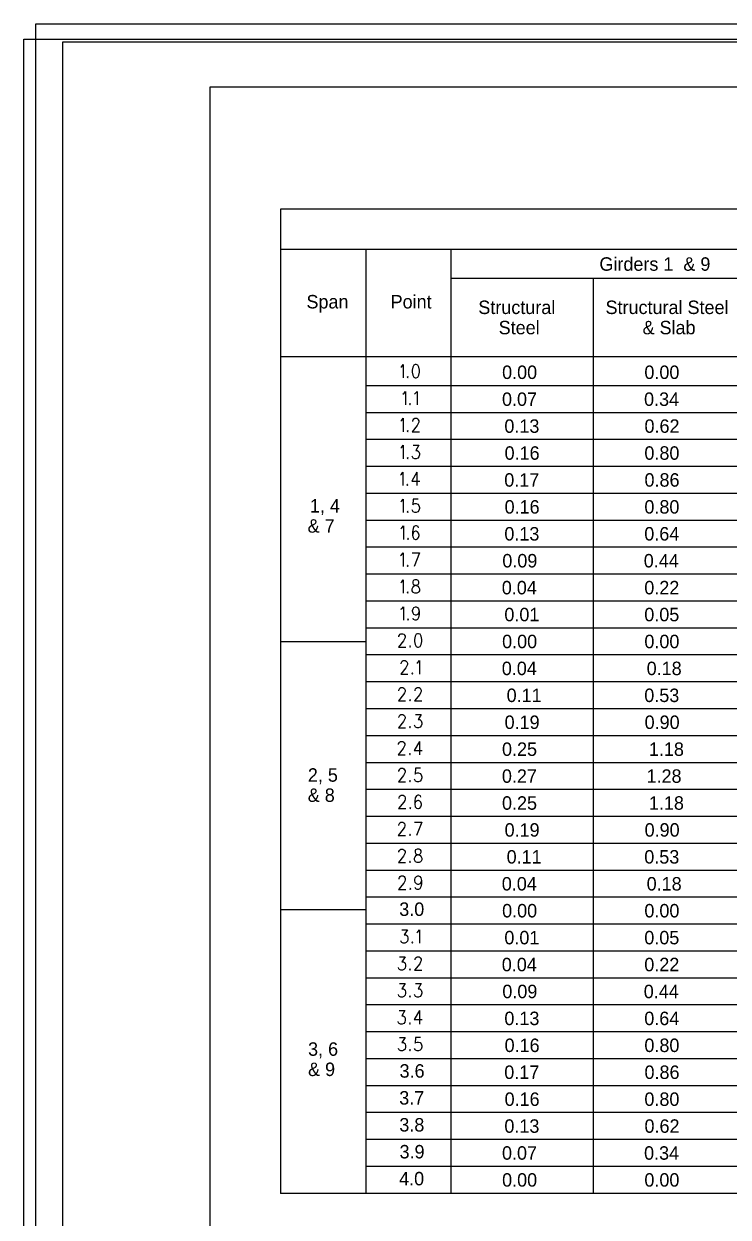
# Model space of a CAD drawing. Extents: x -725.7 to -683.7, y 85.6 to 107.6.
# Drawn here: x -725.67 to -719.13, y 96.51 to 107.6 of the extents above; entities that cross this region are included whole.
import ezdxf

# ---------------------------------------------------------------- set-up
doc = ezdxf.new("R2010")
doc.units = 0
for name, color, linetype in [('border', 7, 'Continuous'), ('Border 2660-Hwy18 - Level 62', 7, 'Continuous'), ('Border 2660-Hwy18 - Level 63', 7, 'Continuous'), ('Level 62 PDF', 7, 'Continuous'), ('Steel', 7, 'Continuous'), ('Text', 7, 'Continuous')]:
    doc.layers.add(name, color=color, linetype=linetype)

msp = doc.modelspace()

# ---------------------------------------------------------------- linework, layer by layer
at = {"layer": 'border'}
for p, q in [((-723.942, 107.01), (-691.93, 107.01)), ((-723.942, 86.465), (-723.942, 107.01))]:
    msp.add_line(p, q, dxfattribs=at)
at = {"layer": 'Border 2660-Hwy18 - Level 62'}
msp.add_lwpolyline([(-725.562, 107.596), (-691.443, 107.596), (-691.443, 85.786), (-725.562, 85.786)], close=True, dxfattribs=at)
at = {"layer": 'Border 2660-Hwy18 - Level 63'}
msp.add_lwpolyline([(-725.673, 107.453), (-691.673, 107.453), (-691.673, 86.083), (-725.673, 86.083)], close=True, dxfattribs=at)
at = {"layer": 'Level 62 PDF'}
msp.add_lwpolyline([(-725.312, 107.429), (-691.193, 107.429), (-691.193, 85.62), (-725.312, 85.62)], close=True, dxfattribs=at)
at = {"layer": 'Steel'}
for p, q in [((-723.289, 105.876), (-723.289, 96.735)), ((-709.806, 105.876), (-723.289, 105.876)), ((-709.806, 105.499), (-723.289, 105.499)), ((-722.496, 105.499), (-722.496, 96.735)), ((-721.704, 105.499), (-721.704, 96.735)), ((-709.806, 105.23), (-721.704, 105.23)), ((-720.382, 105.23), (-720.382, 96.735)), ((-709.806, 104.503), (-723.289, 104.503)), ((-709.806, 104.235), (-722.496, 104.235)), ((-709.806, 103.985), (-722.496, 103.985)), ((-709.806, 103.735), (-722.496, 103.735)), ((-709.806, 103.485), (-722.496, 103.485)), ((-709.806, 103.235), (-722.496, 103.235)), ((-709.806, 102.985), (-722.496, 102.985)), ((-709.806, 102.735), (-722.496, 102.735)), ((-709.806, 102.485), (-722.496, 102.485)), ((-709.806, 102.235), (-722.496, 102.235)), ((-709.806, 101.985), (-722.496, 101.985)), ((-722.496, 101.857), (-723.289, 101.857)), ((-709.806, 101.735), (-722.496, 101.735)), ((-709.806, 101.485), (-722.496, 101.485)), ((-709.806, 101.235), (-722.496, 101.235)), ((-709.806, 100.985), (-722.496, 100.985)), ((-709.806, 100.735), (-722.496, 100.735)), ((-709.806, 100.485), (-722.496, 100.485)), ((-709.806, 100.235), (-722.496, 100.235)), ((-709.806, 99.985), (-722.496, 99.985)), ((-709.806, 99.735), (-722.496, 99.735)), ((-709.806, 99.485), (-722.496, 99.485)), ((-722.496, 99.367), (-723.289, 99.367)), ((-709.806, 99.235), (-722.496, 99.235)), ((-709.806, 98.985), (-722.496, 98.985)), ((-709.806, 98.735), (-722.496, 98.735)), ((-709.806, 98.485), (-722.496, 98.485)), ((-709.806, 98.235), (-722.496, 98.235)), ((-709.806, 97.985), (-722.496, 97.985)), ((-709.806, 97.735), (-722.496, 97.735)), ((-709.806, 97.485), (-722.496, 97.485)), ((-709.806, 97.235), (-722.496, 97.235)), ((-709.806, 96.985), (-722.496, 96.985)), ((-709.806, 96.735), (-723.289, 96.735))]:
    msp.add_line(p, q, dxfattribs=at)
at = {"layer": 'Text'}
for p, q in [((-722.02, 103.433), (-722.02, 103.308)), ((-722.064, 102.683), (-721.997, 102.683)), ((-721.997, 102.683), (-722.045, 102.558)), ((-721.998, 100.933), (-721.998, 100.808)), ((-722.043, 100.183), (-721.976, 100.183)), ((-721.976, 100.183), (-722.024, 100.058)), ((-721.998, 98.433), (-721.998, 98.308))]:
    msp.add_line(p, q, dxfattribs=at)
for points in [[(-722.171, 104.408), (-722.161, 104.415), (-722.147, 104.433), (-722.147, 104.308)], [(-722.036, 104.433), (-722.05, 104.427), (-722.06, 104.408), (-722.064, 104.379), (-722.064, 104.361), (-722.06, 104.332), (-722.05, 104.314), (-722.036, 104.308), (-722.027, 104.308), (-722.012, 104.314), (-722.002, 104.332), (-721.997, 104.361), (-721.997, 104.379), (-722.002, 104.408), (-722.012, 104.427), (-722.027, 104.433), (-722.036, 104.433)], [(-722.105, 104.32), (-722.11, 104.314), (-722.105, 104.308), (-722.101, 104.314), (-722.105, 104.32)], [(-722.15, 104.158), (-722.14, 104.165), (-722.126, 104.183), (-722.126, 104.058)], [(-722.043, 104.158), (-722.033, 104.165), (-722.019, 104.183), (-722.019, 104.058)], [(-722.084, 104.07), (-722.089, 104.064), (-722.084, 104.058), (-722.08, 104.064), (-722.084, 104.07)], [(-722.171, 103.908), (-722.162, 103.915), (-722.148, 103.933), (-722.148, 103.808)], [(-722.06, 103.903), (-722.06, 103.908), (-722.055, 103.92), (-722.05, 103.927), (-722.041, 103.933), (-722.022, 103.933), (-722.012, 103.927), (-722.008, 103.92), (-722.002, 103.908), (-722.002, 103.897), (-722.008, 103.885), (-722.017, 103.867), (-722.064, 103.808), (-721.997, 103.808)], [(-722.106, 103.82), (-722.111, 103.814), (-722.106, 103.808), (-722.101, 103.814), (-722.106, 103.82)], [(-722.171, 103.659), (-722.162, 103.665), (-722.148, 103.683), (-722.148, 103.558)], [(-722.055, 103.683), (-722.002, 103.683), (-722.031, 103.635), (-722.017, 103.635), (-722.008, 103.629), (-722.002, 103.623), (-721.997, 103.605), (-721.997, 103.594), (-722.002, 103.576), (-722.012, 103.564), (-722.027, 103.558), (-722.041, 103.558), (-722.055, 103.564), (-722.06, 103.57), (-722.064, 103.582)], [(-722.106, 103.57), (-722.111, 103.564), (-722.106, 103.558), (-722.101, 103.564), (-722.106, 103.57)], [(-722.174, 103.409), (-722.164, 103.415), (-722.15, 103.433), (-722.15, 103.308)], [(-722.02, 103.433), (-722.067, 103.349), (-721.995, 103.349)], [(-722.108, 103.32), (-722.113, 103.314), (-722.108, 103.308), (-722.104, 103.314), (-722.108, 103.32)], [(-722.171, 103.159), (-722.162, 103.165), (-722.148, 103.183), (-722.148, 103.058)], [(-722.008, 103.183), (-722.055, 103.183), (-722.06, 103.129), (-722.055, 103.135), (-722.041, 103.141), (-722.027, 103.141), (-722.012, 103.135), (-722.002, 103.123), (-721.997, 103.105), (-721.997, 103.094), (-722.002, 103.076), (-722.012, 103.064), (-722.027, 103.058), (-722.041, 103.058), (-722.055, 103.064), (-722.06, 103.07), (-722.064, 103.082)], [(-722.106, 103.07), (-722.111, 103.064), (-722.106, 103.058), (-722.101, 103.064), (-722.106, 103.07)], [(-722.169, 102.909), (-722.16, 102.915), (-722.145, 102.933), (-722.145, 102.808)], [(-722.005, 102.915), (-722.01, 102.927), (-722.024, 102.933), (-722.034, 102.933), (-722.048, 102.927), (-722.057, 102.909), (-722.062, 102.879), (-722.062, 102.849), (-722.057, 102.826), (-722.048, 102.814), (-722.034, 102.808), (-722.029, 102.808), (-722.015, 102.814), (-722.005, 102.826), (-722, 102.844), (-722, 102.849), (-722.005, 102.867), (-722.015, 102.879), (-722.029, 102.885), (-722.034, 102.885), (-722.048, 102.879), (-722.057, 102.867), (-722.062, 102.849)], [(-722.104, 102.82), (-722.108, 102.814), (-722.104, 102.808), (-722.099, 102.814), (-722.104, 102.82)], [(-722.172, 102.659), (-722.163, 102.665), (-722.149, 102.683), (-722.149, 102.558)], [(-722.107, 102.57), (-722.112, 102.564), (-722.107, 102.558), (-722.102, 102.564), (-722.107, 102.57)], [(-722.171, 102.409), (-722.162, 102.415), (-722.148, 102.433), (-722.148, 102.308)], [(-722.041, 102.433), (-722.055, 102.427), (-722.06, 102.415), (-722.06, 102.403), (-722.055, 102.391), (-722.045, 102.385), (-722.027, 102.379), (-722.012, 102.373), (-722.002, 102.361), (-721.997, 102.349), (-721.997, 102.332), (-722.002, 102.32), (-722.008, 102.314), (-722.022, 102.308), (-722.041, 102.308), (-722.055, 102.314), (-722.06, 102.32), (-722.064, 102.332), (-722.064, 102.349), (-722.06, 102.361), (-722.05, 102.373), (-722.036, 102.379), (-722.017, 102.385), (-722.008, 102.391), (-722.002, 102.403), (-722.002, 102.415), (-722.008, 102.427), (-722.022, 102.433), (-722.041, 102.433)], [(-722.106, 102.32), (-722.111, 102.314), (-722.106, 102.308), (-722.101, 102.314), (-722.106, 102.32)], [(-722.169, 102.159), (-722.16, 102.165), (-722.145, 102.183), (-722.145, 102.058)], [(-722, 102.141), (-722.005, 102.123), (-722.015, 102.111), (-722.029, 102.105), (-722.034, 102.105), (-722.048, 102.111), (-722.057, 102.123), (-722.062, 102.141), (-722.062, 102.147), (-722.057, 102.165), (-722.048, 102.177), (-722.034, 102.183), (-722.029, 102.183), (-722.015, 102.177), (-722.005, 102.165), (-722, 102.141), (-722, 102.111), (-722.005, 102.082), (-722.015, 102.064), (-722.029, 102.058), (-722.038, 102.058), (-722.053, 102.064), (-722.057, 102.076)], [(-722.104, 102.07), (-722.108, 102.064), (-722.104, 102.058), (-722.099, 102.064), (-722.104, 102.07)], [(-722.188, 101.903), (-722.188, 101.909), (-722.183, 101.92), (-722.178, 101.927), (-722.169, 101.933), (-722.15, 101.933), (-722.14, 101.927), (-722.136, 101.92), (-722.13, 101.909), (-722.13, 101.897), (-722.136, 101.885), (-722.145, 101.867), (-722.192, 101.808), (-722.125, 101.808)], [(-722.014, 101.933), (-722.029, 101.927), (-722.038, 101.909), (-722.043, 101.879), (-722.043, 101.861), (-722.038, 101.832), (-722.029, 101.814), (-722.014, 101.808), (-722.005, 101.808), (-721.991, 101.814), (-721.981, 101.832), (-721.976, 101.861), (-721.976, 101.879), (-721.981, 101.909), (-721.991, 101.927), (-722.005, 101.933), (-722.014, 101.933)], [(-722.084, 101.82), (-722.088, 101.814), (-722.084, 101.808), (-722.079, 101.814), (-722.084, 101.82)], [(-722.167, 101.653), (-722.167, 101.659), (-722.162, 101.67), (-722.157, 101.677), (-722.148, 101.683), (-722.129, 101.683), (-722.119, 101.677), (-722.115, 101.67), (-722.109, 101.659), (-722.109, 101.647), (-722.115, 101.635), (-722.124, 101.617), (-722.171, 101.558), (-722.104, 101.558)], [(-722.021, 101.659), (-722.012, 101.665), (-721.997, 101.683), (-721.997, 101.558)], [(-722.063, 101.57), (-722.067, 101.564), (-722.063, 101.558), (-722.058, 101.564), (-722.063, 101.57)], [(-722.188, 101.403), (-722.188, 101.409), (-722.184, 101.42), (-722.179, 101.427), (-722.169, 101.433), (-722.151, 101.433), (-722.141, 101.427), (-722.136, 101.42), (-722.131, 101.409), (-722.131, 101.397), (-722.136, 101.385), (-722.146, 101.367), (-722.193, 101.308), (-722.126, 101.308)], [(-722.038, 101.403), (-722.038, 101.409), (-722.033, 101.42), (-722.029, 101.427), (-722.019, 101.433), (-722, 101.433), (-721.991, 101.427), (-721.986, 101.42), (-721.981, 101.409), (-721.981, 101.397), (-721.986, 101.385), (-721.995, 101.367), (-722.043, 101.308), (-721.976, 101.308)], [(-722.084, 101.32), (-722.089, 101.314), (-722.084, 101.308), (-722.08, 101.314), (-722.084, 101.32)], [(-722.188, 101.153), (-722.188, 101.159), (-722.184, 101.17), (-722.179, 101.177), (-722.169, 101.183), (-722.151, 101.183), (-722.141, 101.177), (-722.136, 101.17), (-722.131, 101.159), (-722.131, 101.147), (-722.136, 101.135), (-722.146, 101.117), (-722.193, 101.058), (-722.126, 101.058)], [(-722.033, 101.183), (-721.981, 101.183), (-722.01, 101.135), (-721.995, 101.135), (-721.986, 101.129), (-721.981, 101.123), (-721.976, 101.105), (-721.976, 101.094), (-721.981, 101.076), (-721.991, 101.064), (-722.005, 101.058), (-722.019, 101.058), (-722.033, 101.064), (-722.038, 101.07), (-722.043, 101.082)], [(-722.084, 101.07), (-722.089, 101.064), (-722.084, 101.058), (-722.08, 101.064), (-722.084, 101.07)], [(-722.191, 100.903), (-722.191, 100.909), (-722.186, 100.92), (-722.181, 100.927), (-722.172, 100.933), (-722.153, 100.933), (-722.143, 100.927), (-722.139, 100.92), (-722.133, 100.909), (-722.133, 100.897), (-722.139, 100.885), (-722.148, 100.867), (-722.195, 100.808), (-722.129, 100.808)], [(-721.998, 100.933), (-722.045, 100.849), (-721.973, 100.849)], [(-722.087, 100.82), (-722.091, 100.814), (-722.087, 100.808), (-722.082, 100.814), (-722.087, 100.82)], [(-722.188, 100.653), (-722.188, 100.659), (-722.184, 100.67), (-722.179, 100.677), (-722.169, 100.683), (-722.151, 100.683), (-722.141, 100.677), (-722.136, 100.67), (-722.131, 100.659), (-722.131, 100.647), (-722.136, 100.635), (-722.146, 100.617), (-722.193, 100.558), (-722.126, 100.558)], [(-721.986, 100.683), (-722.033, 100.683), (-722.038, 100.629), (-722.033, 100.635), (-722.019, 100.641), (-722.005, 100.641), (-721.991, 100.635), (-721.981, 100.623), (-721.976, 100.605), (-721.976, 100.594), (-721.981, 100.576), (-721.991, 100.564), (-722.005, 100.558), (-722.019, 100.558), (-722.033, 100.564), (-722.038, 100.57), (-722.043, 100.582)], [(-722.084, 100.57), (-722.089, 100.564), (-722.084, 100.558), (-722.08, 100.564), (-722.084, 100.57)], [(-722.186, 100.403), (-722.186, 100.409), (-722.181, 100.42), (-722.177, 100.427), (-722.167, 100.433), (-722.148, 100.433), (-722.139, 100.427), (-722.134, 100.42), (-722.129, 100.409), (-722.129, 100.397), (-722.134, 100.385), (-722.143, 100.367), (-722.191, 100.308), (-722.124, 100.308)], [(-721.983, 100.415), (-721.988, 100.427), (-722.003, 100.433), (-722.012, 100.433), (-722.026, 100.427), (-722.036, 100.409), (-722.04, 100.379), (-722.04, 100.349), (-722.036, 100.326), (-722.026, 100.314), (-722.012, 100.308), (-722.007, 100.308), (-721.993, 100.314), (-721.983, 100.326), (-721.978, 100.344), (-721.978, 100.349), (-721.983, 100.367), (-721.993, 100.379), (-722.007, 100.385), (-722.012, 100.385), (-722.026, 100.379), (-722.036, 100.367), (-722.04, 100.349)], [(-722.082, 100.32), (-722.087, 100.314), (-722.082, 100.308), (-722.077, 100.314), (-722.082, 100.32)], [(-722.189, 100.153), (-722.189, 100.159), (-722.184, 100.17), (-722.18, 100.177), (-722.17, 100.183), (-722.151, 100.183), (-722.142, 100.177), (-722.137, 100.17), (-722.132, 100.159), (-722.132, 100.147), (-722.137, 100.135), (-722.147, 100.117), (-722.194, 100.058), (-722.127, 100.058)], [(-722.085, 100.07), (-722.09, 100.064), (-722.085, 100.058), (-722.08, 100.064), (-722.085, 100.07)], [(-722.188, 99.903), (-722.188, 99.909), (-722.184, 99.92), (-722.179, 99.927), (-722.169, 99.933), (-722.151, 99.933), (-722.141, 99.927), (-722.136, 99.92), (-722.131, 99.909), (-722.131, 99.897), (-722.136, 99.885), (-722.146, 99.867), (-722.193, 99.808), (-722.126, 99.808)], [(-722.019, 99.933), (-722.033, 99.927), (-722.038, 99.915), (-722.038, 99.903), (-722.033, 99.891), (-722.024, 99.885), (-722.005, 99.879), (-721.991, 99.873), (-721.981, 99.861), (-721.976, 99.849), (-721.976, 99.832), (-721.981, 99.82), (-721.986, 99.814), (-722, 99.808), (-722.019, 99.808), (-722.033, 99.814), (-722.038, 99.82), (-722.043, 99.832), (-722.043, 99.849), (-722.038, 99.861), (-722.029, 99.873), (-722.014, 99.879), (-721.995, 99.885), (-721.986, 99.891), (-721.981, 99.903), (-721.981, 99.915), (-721.986, 99.927), (-722, 99.933), (-722.019, 99.933)], [(-722.084, 99.82), (-722.089, 99.814), (-722.084, 99.808), (-722.08, 99.814), (-722.084, 99.82)], [(-722.186, 99.653), (-722.186, 99.659), (-722.181, 99.67), (-722.177, 99.677), (-722.167, 99.683), (-722.148, 99.683), (-722.139, 99.677), (-722.134, 99.67), (-722.129, 99.659), (-722.129, 99.647), (-722.134, 99.635), (-722.143, 99.617), (-722.191, 99.558), (-722.124, 99.558)], [(-721.978, 99.641), (-721.984, 99.623), (-721.993, 99.611), (-722.007, 99.605), (-722.012, 99.605), (-722.026, 99.611), (-722.036, 99.623), (-722.04, 99.641), (-722.04, 99.647), (-722.036, 99.665), (-722.026, 99.677), (-722.012, 99.683), (-722.007, 99.683), (-721.993, 99.677), (-721.984, 99.665), (-721.978, 99.641), (-721.978, 99.611), (-721.984, 99.582), (-721.993, 99.564), (-722.007, 99.558), (-722.017, 99.558), (-722.031, 99.564), (-722.036, 99.576)], [(-722.082, 99.57), (-722.087, 99.564), (-722.082, 99.558), (-722.077, 99.564), (-722.082, 99.57)], [(-722.162, 99.183), (-722.109, 99.183), (-722.138, 99.135), (-722.124, 99.135), (-722.115, 99.129), (-722.109, 99.123), (-722.104, 99.105), (-722.104, 99.094), (-722.109, 99.076), (-722.119, 99.064), (-722.134, 99.058), (-722.148, 99.058), (-722.162, 99.064), (-722.167, 99.07), (-722.171, 99.082)], [(-722.021, 99.159), (-722.012, 99.165), (-721.997, 99.183), (-721.997, 99.058)], [(-722.063, 99.07), (-722.067, 99.064), (-722.063, 99.058), (-722.058, 99.064), (-722.063, 99.07)], [(-722.184, 98.933), (-722.131, 98.933), (-722.16, 98.885), (-722.146, 98.885), (-722.136, 98.879), (-722.131, 98.873), (-722.126, 98.855), (-722.126, 98.844), (-722.131, 98.826), (-722.141, 98.814), (-722.155, 98.808), (-722.169, 98.808), (-722.184, 98.814), (-722.188, 98.82), (-722.193, 98.832)], [(-722.038, 98.903), (-722.038, 98.909), (-722.033, 98.92), (-722.029, 98.927), (-722.019, 98.933), (-722, 98.933), (-721.991, 98.927), (-721.986, 98.92), (-721.981, 98.909), (-721.981, 98.897), (-721.986, 98.885), (-721.995, 98.867), (-722.043, 98.808), (-721.976, 98.808)], [(-722.084, 98.82), (-722.089, 98.814), (-722.084, 98.808), (-722.08, 98.814), (-722.084, 98.82)], [(-722.184, 98.683), (-722.131, 98.683), (-722.16, 98.635), (-722.146, 98.635), (-722.136, 98.629), (-722.131, 98.623), (-722.126, 98.605), (-722.126, 98.594), (-722.131, 98.576), (-722.141, 98.564), (-722.155, 98.558), (-722.169, 98.558), (-722.184, 98.564), (-722.188, 98.57), (-722.193, 98.582)], [(-722.033, 98.683), (-721.981, 98.683), (-722.01, 98.635), (-721.995, 98.635), (-721.986, 98.629), (-721.981, 98.623), (-721.976, 98.605), (-721.976, 98.594), (-721.981, 98.576), (-721.991, 98.564), (-722.005, 98.558), (-722.019, 98.558), (-722.033, 98.564), (-722.038, 98.57), (-722.043, 98.582)], [(-722.084, 98.57), (-722.089, 98.564), (-722.084, 98.558), (-722.08, 98.564), (-722.084, 98.57)], [(-722.186, 98.433), (-722.133, 98.433), (-722.162, 98.385), (-722.148, 98.385), (-722.139, 98.379), (-722.133, 98.373), (-722.129, 98.355), (-722.129, 98.344), (-722.133, 98.326), (-722.143, 98.314), (-722.158, 98.308), (-722.172, 98.308), (-722.186, 98.314), (-722.191, 98.32), (-722.195, 98.332)], [(-721.998, 98.433), (-722.045, 98.349), (-721.973, 98.349)], [(-722.087, 98.32), (-722.091, 98.314), (-722.087, 98.308), (-722.082, 98.314), (-722.087, 98.32)], [(-722.184, 98.183), (-722.131, 98.183), (-722.16, 98.135), (-722.146, 98.135), (-722.136, 98.129), (-722.131, 98.123), (-722.126, 98.105), (-722.126, 98.094), (-722.131, 98.076), (-722.141, 98.064), (-722.155, 98.058), (-722.169, 98.058), (-722.184, 98.064), (-722.188, 98.07), (-722.193, 98.082)], [(-721.986, 98.183), (-722.033, 98.183), (-722.038, 98.129), (-722.033, 98.135), (-722.019, 98.141), (-722.005, 98.141), (-721.991, 98.135), (-721.981, 98.123), (-721.976, 98.105), (-721.976, 98.094), (-721.981, 98.076), (-721.991, 98.064), (-722.005, 98.058), (-722.019, 98.058), (-722.033, 98.064), (-722.038, 98.07), (-722.043, 98.082)], [(-722.084, 98.07), (-722.089, 98.064), (-722.084, 98.058), (-722.08, 98.064), (-722.084, 98.07)]]:
    msp.add_lwpolyline(points, dxfattribs=at)

# ---------------------------------------------------------------- texts
for s, p in [('Girders 1  & 9', (-720.325, 105.303)), ('Span', (-723.047, 104.953)), ('Point', (-722.265, 104.953)), ('Structural', (-721.45, 104.901)), ('Structural Steel', (-720.268, 104.901)), ('Steel', (-721.261, 104.713)), ('& Slab', (-719.924, 104.713)), ('0.00', (-721.229, 104.298)), ('0.00', (-719.907, 104.298)), ('0.07', (-721.23, 104.048)), ('0.34', (-719.91, 104.048)), ('0.13', (-721.208, 103.798)), ('0.62', (-719.906, 103.798)), ('0.16', (-721.206, 103.548)), ('0.80', (-719.907, 103.548)), ('0.17', (-721.209, 103.298)), ('0.86', (-719.906, 103.298)), ('1, 4', (-723.015, 103.058)), ('0.16', (-721.206, 103.048)), ('0.80', (-719.907, 103.048)), ('& 7', (-723.036, 102.871)), ('0.13', (-721.208, 102.798)), ('0.64', (-719.908, 102.798)), ('0.09', (-721.227, 102.548)), ('0.44', (-719.913, 102.548)), ('0.04', (-721.232, 102.298)), ('0.22', (-719.908, 102.298)), ('0.01', (-721.208, 102.048)), ('0.05', (-719.908, 102.048)), ('0.00', (-721.229, 101.798)), ('0.00', (-719.907, 101.798)), ('0.04', (-721.232, 101.548)), ('0.18', (-719.886, 101.548)), ('0.11', (-721.187, 101.298)), ('0.53', (-719.908, 101.298)), ('0.19', (-721.206, 101.048)), ('0.90', (-719.905, 101.048)), ('0.25', (-721.23, 100.798)), ('1.18', (-719.865, 100.798)), ('2, 5', (-723.034, 100.558)), ('0.27', (-721.231, 100.548)), ('1.28', (-719.887, 100.548)), ('& 8', (-723.035, 100.371)), ('0.25', (-721.23, 100.298)), ('1.18', (-719.865, 100.298)), ('0.19', (-721.206, 100.048)), ('0.90', (-719.905, 100.048)), ('0.11', (-721.187, 99.798)), ('0.53', (-719.908, 99.798)), ('0.04', (-721.232, 99.548)), ('0.18', (-719.886, 99.548)), ('3.0', (-722.185, 99.312)), ('0.00', (-721.229, 99.298)), ('0.00', (-719.907, 99.298)), ('0.01', (-721.208, 99.048)), ('0.05', (-719.908, 99.048)), ('0.04', (-721.232, 98.798)), ('0.22', (-719.908, 98.798)), ('0.09', (-721.227, 98.548)), ('0.44', (-719.913, 98.548)), ('0.13', (-721.208, 98.298)), ('0.64', (-719.908, 98.298)), ('3, 6', (-723.032, 98.013)), ('0.16', (-721.206, 98.048)), ('0.80', (-719.907, 98.048)), ('& 9', (-723.032, 97.825)), ('3.6', (-722.182, 97.81)), ('0.17', (-721.209, 97.798)), ('0.86', (-719.906, 97.798)), ('3.7', (-722.185, 97.56)), ('0.16', (-721.206, 97.548)), ('0.80', (-719.907, 97.548)), ('3.8', (-722.184, 97.31)), ('0.13', (-721.208, 97.298)), ('0.62', (-719.906, 97.298)), ('3.9', (-722.182, 97.06)), ('0.07', (-721.23, 97.048)), ('0.34', (-719.91, 97.048)), ('4.0', (-722.186, 96.81)), ('0.00', (-721.229, 96.798)), ('0.00', (-719.907, 96.798))]:
    msp.add_text(s, height=0.125, dxfattribs=at).set_placement(p)

doc.saveas('drawing.dxf')
